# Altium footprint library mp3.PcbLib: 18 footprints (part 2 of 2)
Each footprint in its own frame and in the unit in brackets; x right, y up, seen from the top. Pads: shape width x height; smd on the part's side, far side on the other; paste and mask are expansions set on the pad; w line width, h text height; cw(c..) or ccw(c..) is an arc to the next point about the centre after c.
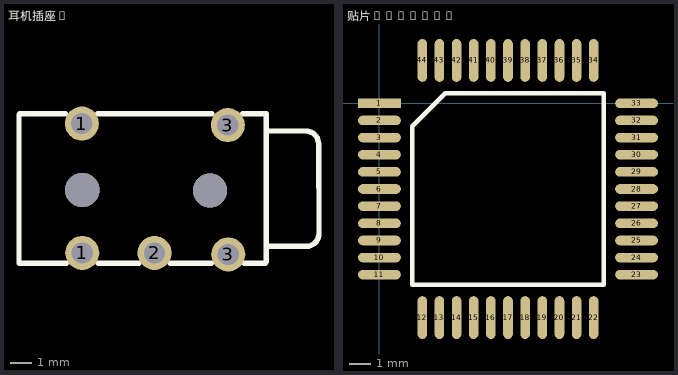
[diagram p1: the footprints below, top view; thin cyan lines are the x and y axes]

## 耳机插座3 [mm]
pads (5):
  round 1.6 hole 1: 1(-12.329,-5.594) 1(-12.309,-11.669) 2(-8.917,-11.669) 3(-5.474,-5.664) 3(-5.454,-11.739)
via -6.315,-8.737 diameter 1.6 hole 1.6
via -12.309,-8.707 diameter 1.6 hole 1.6
Top Overlay:
  lines w0.254: -15.282,-5.184 -15.282,-12.149 -13.06,-12.149 ; -15.242,-5.124 -13.11,-5.124 ; -11.589,-5.124 -6.215,-5.124 ; -11.559,-12.149 -9.657,-12.149 ; -8.176,-12.149 -6.255,-12.149 ; -4.784,-5.124 -3.663,-5.124 -3.663,-12.089 ; -4.694,-12.149 -3.703,-12.149 ; -3.643,-5.945 -1.821,-5.945 cw(c-1.811,-6.545) -1.211,-6.535 -1.191,-10.748 cw(c-1.791,-10.758) -1.781,-11.359 -3.603,-11.359

## 贴片Mega16L [mm]
pads (44):
  rect 2x0.45 smd: 1(0,0)
  oval 2x0.45 smd: 2(0,-0.8) 3(0,-1.6) 4(0,-2.4) 5(0,-3.2) 6(0,-4) 7(0,-4.8) 8(0,-5.6) 9(0,-6.4) 10(0,-7.2) 11(0,-8) 23(12,-8) 24(12,-7.2) 25(12,-6.4) 26(12,-5.6) 27(12,-4.8) 28(12,-4) 29(12,-3.2) 30(12,-2.4) 31(12,-1.6) 32(12,-0.8) 33(12,0)
  oval 0.45x2 smd: 12(2,-10) 13(2.8,-10) 14(3.6,-10) 15(4.4,-10) 16(5.2,-10) 17(6,-10) 18(6.8,-10) 19(7.6,-10) 20(8.4,-10) 21(9.2,-10) 22(10,-10) 34(10,2) 35(9.2,2) 36(8.4,2) 37(7.6,2) 38(6.8,2) 39(6,2) 40(5.2,2) 41(4.4,2) 42(3.6,2) 43(2.8,2) 44(2,2)
Top Overlay:
  lines w0.2: 1.535,-8.465 1.535,-1.07 3.07,0.465 10.465,0.465 10.465,-8.465 1.535,-8.465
